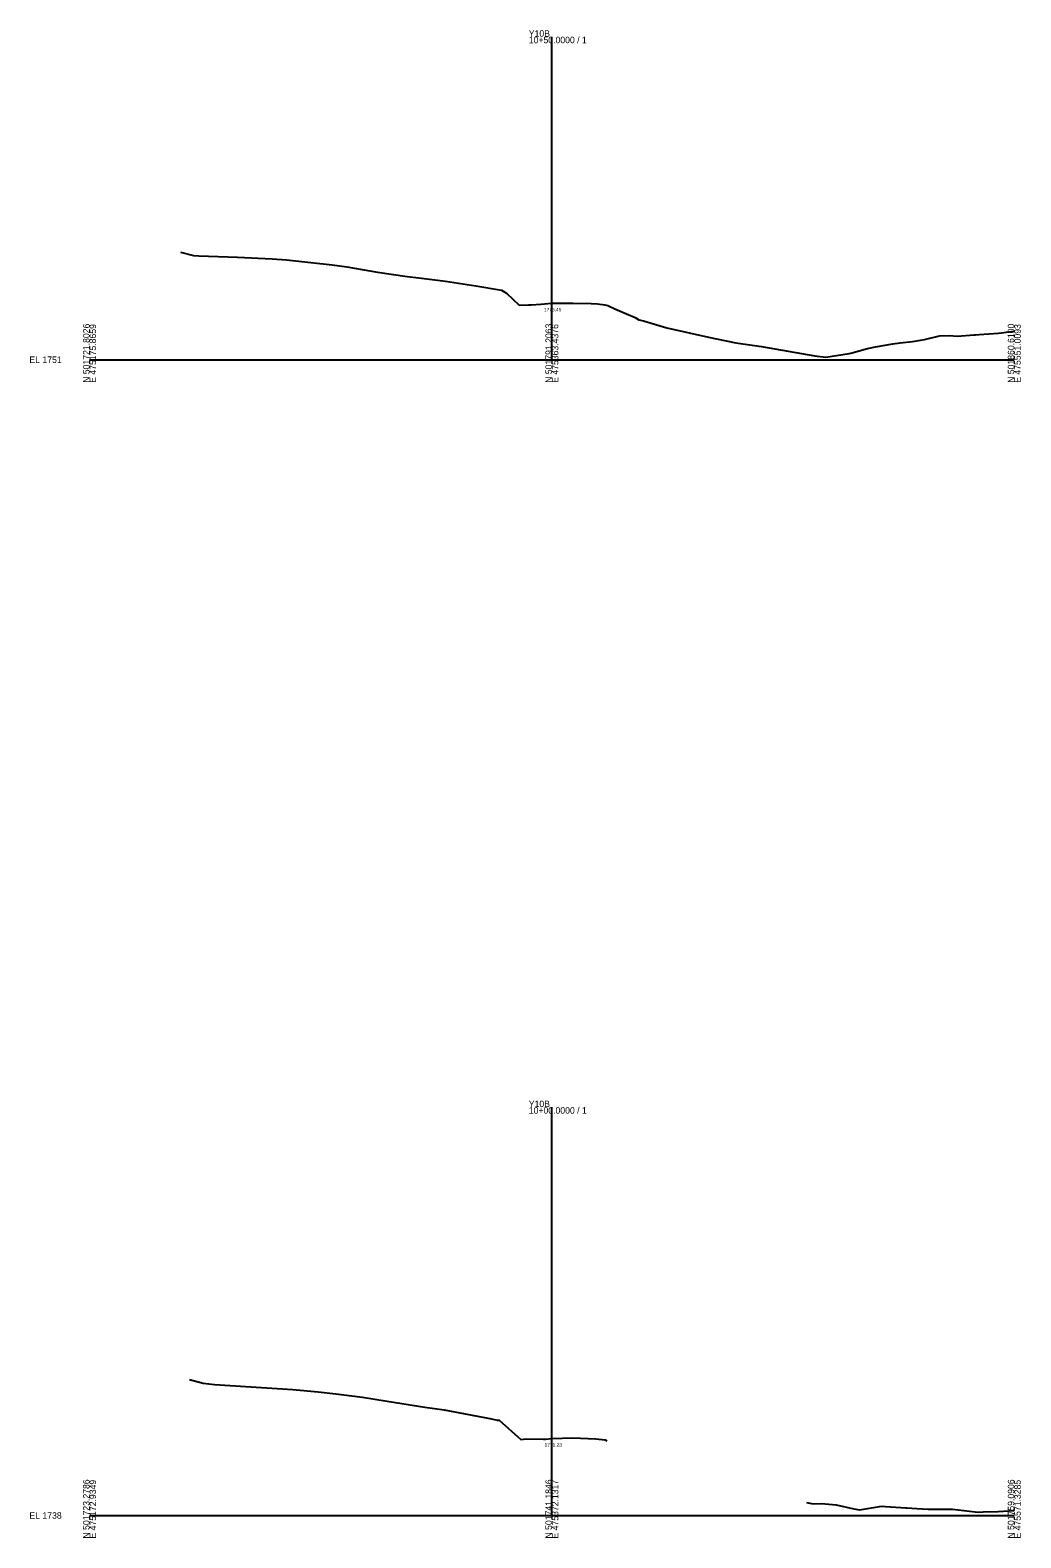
# Model space of a CAD drawing. Extents: x -26 to 1803, y -10 to 9558.
# Drawn here: x -26 to 403, y -10 to 643 of the extents above; entities that cross this region are included whole.
import ezdxf

# ---------------------------------------------------------------- set-up
doc = ezdxf.new("R2010")
doc.units = 0
for name, color, linetype in [('Exist Cross Section Cell', 7, 'Continuous'), ('Exist XS Center Line Elevation Label', 7, 'Continuous'), ('Exist XS Ground Line', 7, 'Continuous')]:
    doc.layers.add(name, color=color, linetype=linetype)

msp = doc.modelspace()

# ---------------------------------------------------------------- linework, layer by layer
at = {"layer": 'Exist Cross Section Cell'}
for p, q in [((200, 500), (200, 639.74)), ((0, 500), (200, 500)), ((200, 500), (400, 500)), ((200, 0), (200, 176.64)), ((0, 0), (200, 0)), ((200, 0), (400, 0))]:
    msp.add_line(p, q, dxfattribs=at)
at = {"layer": 'Exist XS Ground Line'}
for points in [[(39.41, 546.58), (44.96, 545.06), (47.29, 544.95), (63.98, 544.33), (78.93, 543.67), (85.14, 543.24), (104.91, 541.04), (111.26, 540.24), (124.59, 537.93), (137.37, 535.96), (142.37, 535.47), (154.02, 534.03), (167.08, 531.9), (178.18, 530.06), (180.36, 528.79), (185.86, 523.56), (189.92, 523.75), (191.03, 523.81), (195.27, 524.09), (199.8, 524.45), (205.44, 524.46), (209.21, 524.53), (217.05, 524.3), (219.75, 524.25), (222.92, 523.7), (224.25, 523.43), (227.18, 522.08), (231.23, 520.32), (236.06, 518.2), (237.55, 517.31), (239.66, 516.78), (249.75, 513.85), (267.67, 509.71), (279.56, 507.35), (290.66, 505.7), (313.71, 501.7), (318.51, 501.04), (328.64, 502.68), (329.24, 502.87), (336.46, 504.87), (339.9, 505.57), (347.4, 506.88), (350.57, 507.29), (355.97, 507.95), (361.23, 508.69), (367.6, 510.39), (371.9, 510.44), (375.38, 510.22), (382.56, 510.79), (383.17, 510.84), (384.8, 510.95), (393.23, 511.56), (398.74, 512.19), (400, 512.31)], [(43.27, 58.88), (49.13, 57.22), (54.03, 56.59), (87.93, 54.45), (98.83, 53.53), (106.54, 52.68), (118.03, 51.21), (128.67, 49.48), (145.06, 46.89), (153.34, 45.68), (173.88, 41.81), (176.32, 41.29), (177.14, 41.26), (186.54, 32.88), (188.92, 33.17), (196.34, 32.96), (197.2, 33.03), (200, 33.23), (209.02, 33.52), (219.06, 33.1), (223.06, 32.74), (223.72, 32.26)], [(310.09, 5.65), (312.97, 5.01), (316.67, 5.15), (323.01, 4.59), (330.61, 2.93), (333.05, 2.38), (341.64, 3.92), (343.1, 4.02), (344.31, 3.92), (353.14, 3.3), (353.52, 3.28), (357.83, 3.03), (362.74, 2.74), (363.18, 2.74), (371.95, 2.74), (373.22, 2.74), (378.2, 2.1), (383.02, 1.53), (384.44, 1.48), (386.61, 1.56), (393.02, 1.66), (400, 2.13)]]:
    msp.add_lwpolyline(points, dxfattribs=at)

# ---------------------------------------------------------------- texts
at = {"layer": 'Exist Cross Section Cell'}
for s, p in [('Y10B', (190, 639.74)), ('10+50.0000 / 1', (190, 636.94)), ('EL 1751', (-26, 498.6)), ('Y10B', (190, 176.64)), ('10+00.0000 / 1', (190, 173.84)), ('EL 1738', (-26, -1.4))]:
    msp.add_text(s, height=2.8, dxfattribs=at).set_placement(p)
for s, p in [('N 501721.8026', (0, 490)), ('N 501791.2063', (200, 490)), ('N 501860.6100', (400, 490)), ('E 475175.8659', (2.8, 490)), ('E 475363.4376', (202.8, 490)), ('E 475551.0093', (402.8, 490)), ('N 501723.2786', (0, -10)), ('E 475172.9349', (2.8, -10)), ('N 501741.1846', (200, -10)), ('E 475372.1317', (202.8, -10)), ('N 501759.0906', (400, -10)), ('E 475571.3285', (402.8, -10))]:
    msp.add_text(s, height=2.8, rotation=90, dxfattribs=at).set_placement(p)
at = {"layer": 'Exist XS Center Line Elevation Label'}
for s, p in [('1775.45', (196.57, 520.95)), ('1771.23', (196.82, 29.73))]:
    msp.add_text(s, height=1.5, dxfattribs=at).set_placement(p)

doc.saveas('drawing.dxf')
